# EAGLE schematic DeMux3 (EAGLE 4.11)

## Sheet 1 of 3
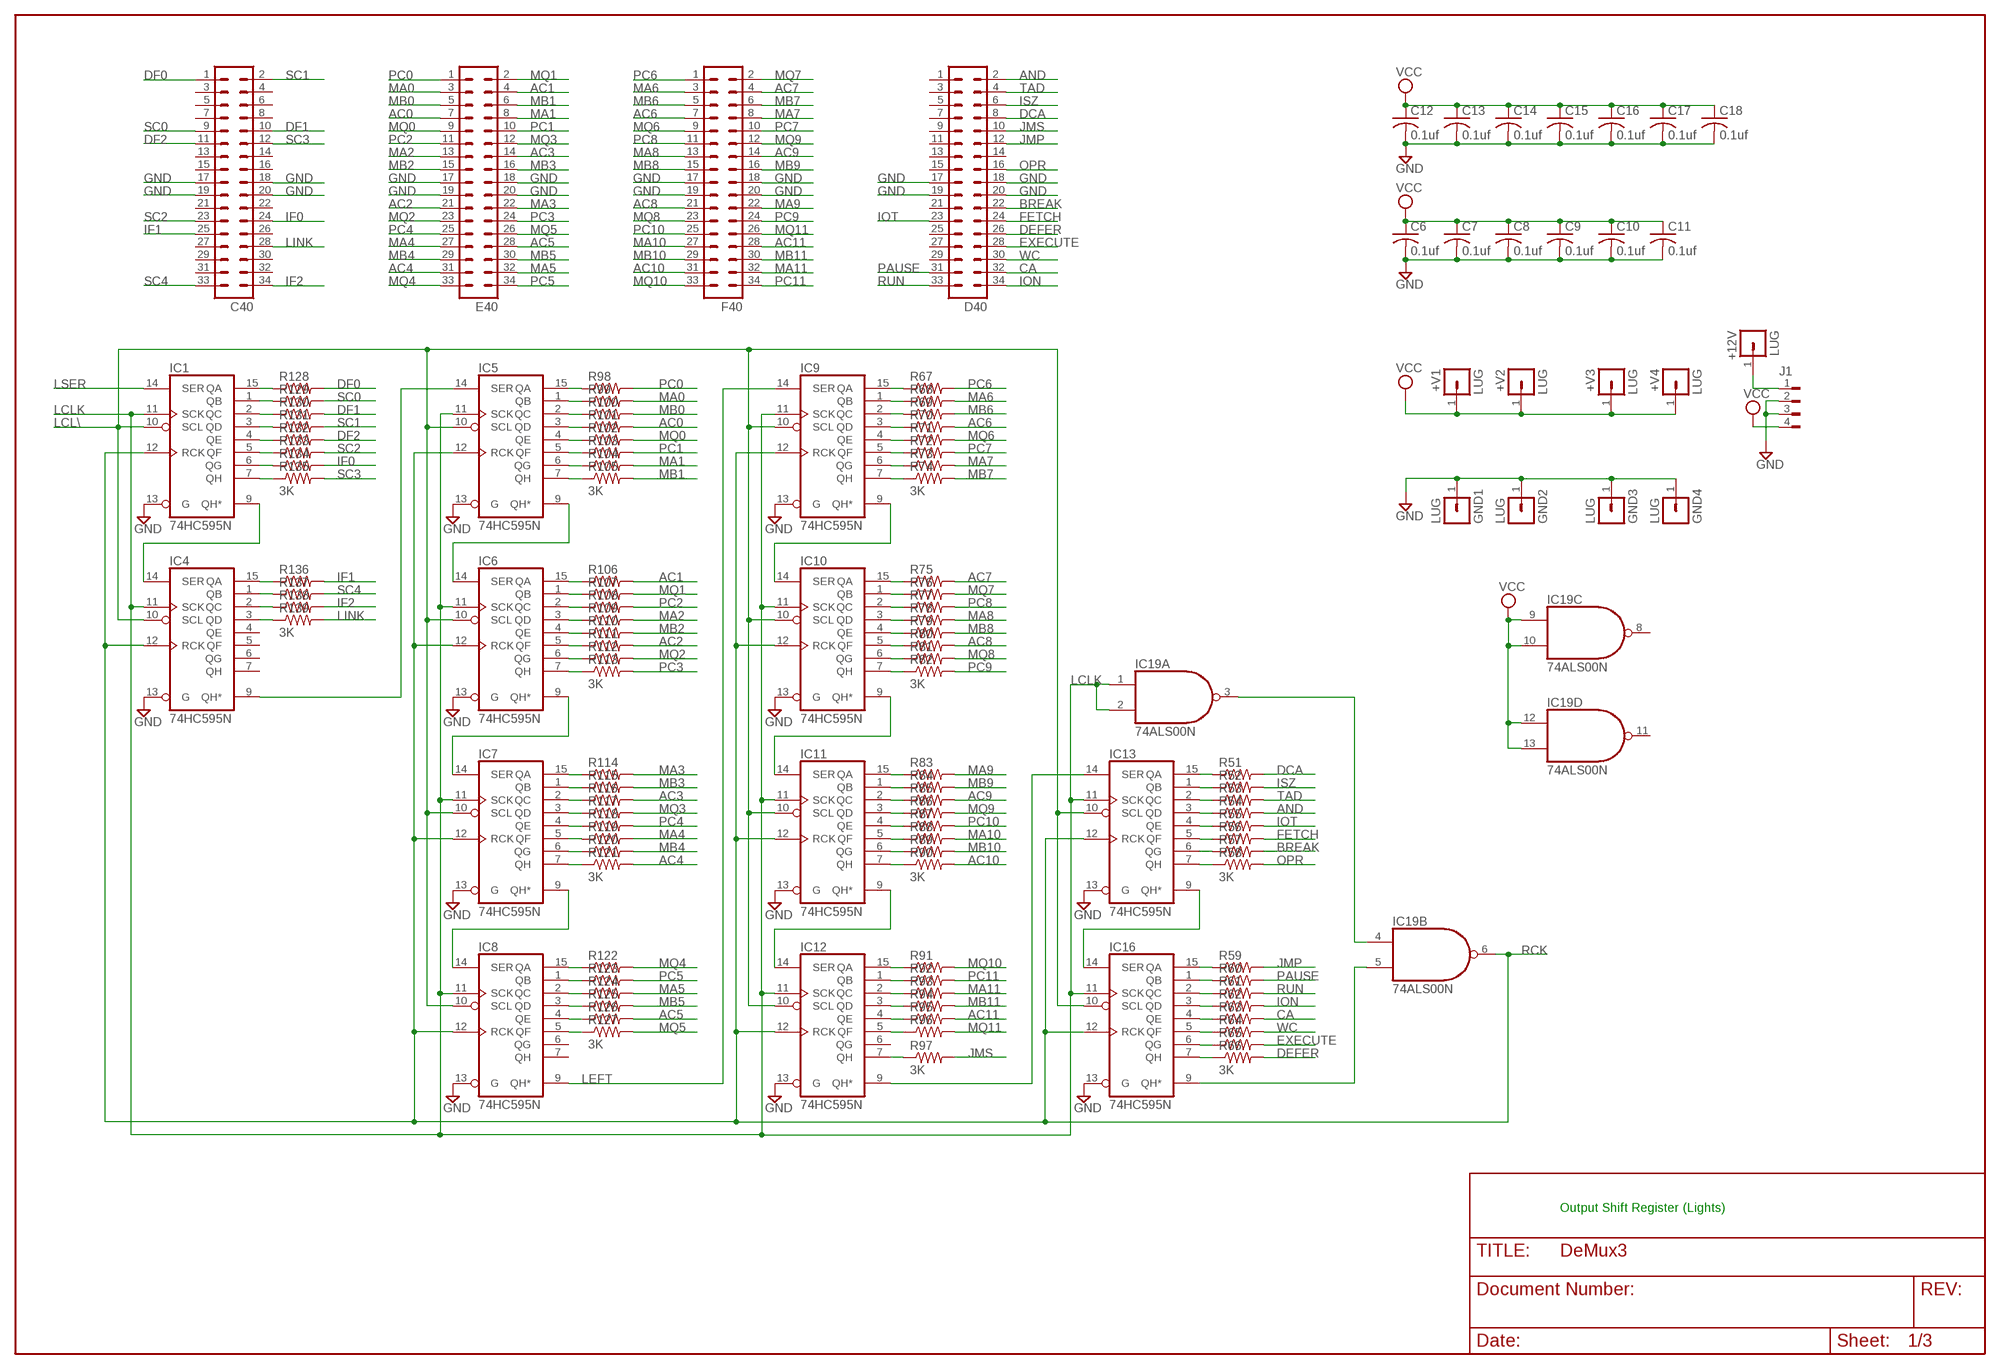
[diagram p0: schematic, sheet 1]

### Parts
+12V  LUG  [SPADELUG]
+V1  LUG  [SPADELUG]
+V2  LUG  [SPADELUG]
+V3  LUG  [SPADELUG]
+V4  LUG  [SPADELUG]
C6  0.1uf  C-US050-025X075  [C050-025X075]
C7  0.1uf  C-US050-025X075  [C050-025X075]
C8  0.1uf  C-US050-025X075  [C050-025X075]
C9  0.1uf  C-US050-025X075  [C050-025X075]
C10  0.1uf  C-US050-025X075  [C050-025X075]
C11  0.1uf  C-US050-025X075  [C050-025X075]
C12  0.1uf  C-US050-025X075  [C050-025X075]
C13  0.1uf  C-US050-025X075  [C050-025X075]
C14  0.1uf  C-US050-025X075  [C050-025X075]
C15  0.1uf  C-US050-025X075  [C050-025X075]
C16  0.1uf  C-US050-025X075  [C050-025X075]
C17  0.1uf  C-US050-025X075  [C050-025X075]
C18  0.1uf  C-US050-025X075  [C050-025X075]
C40  MA17-2  [MA17-2]
D40  MA17-2  [MA17-2]
E40  MA17-2  [MA17-2]
F40  MA17-2  [MA17-2]
GND1  LUG  [SPADELUG]
GND2  LUG  [SPADELUG]
GND3  LUG  [SPADELUG]
GND4  LUG  [SPADELUG]
IC1  74HC595N  74LS595N  [DIL16]
IC4  74HC595N  74LS595N  [DIL16]
IC5  74HC595N  74LS595N  [DIL16]
IC6  74HC595N  74LS595N  [DIL16]
IC7  74HC595N  74LS595N  [DIL16]
IC8  74HC595N  74LS595N  [DIL16]
IC9  74HC595N  74LS595N  [DIL16]
IC10  74HC595N  74LS595N  [DIL16]
IC11  74HC595N  74LS595N  [DIL16]
IC12  74HC595N  74LS595N  [DIL16]
IC13  74HC595N  74LS595N  [DIL16]
IC16  74HC595N  74LS595N  [DIL16]
IC19  74ALS00N  [DIL14]
J1  FLOPPY-4  [FLOPPY-4]
R51  R-US_0207/10  [0207/10]
R52  R-US_0207/10  [0207/10]
R53  R-US_0207/10  [0207/10]
R54  R-US_0207/10  [0207/10]
R55  R-US_0207/10  [0207/10]
R56  R-US_0207/10  [0207/10]
R57  R-US_0207/10  [0207/10]
R58  3K  R-US_0207/10  [0207/10]
R59  R-US_0207/10  [0207/10]
R60  R-US_0207/10  [0207/10]
R61  R-US_0207/10  [0207/10]
R62  R-US_0207/10  [0207/10]
R63  R-US_0207/10  [0207/10]
R64  R-US_0207/10  [0207/10]
R65  R-US_0207/10  [0207/10]
R66  3K  R-US_0207/10  [0207/10]
R67  R-US_0207/10  [0207/10]
R68  R-US_0207/10  [0207/10]
R69  R-US_0207/10  [0207/10]
R70  R-US_0207/10  [0207/10]
R71  R-US_0207/10  [0207/10]
R72  R-US_0207/10  [0207/10]
R73  R-US_0207/10  [0207/10]
R74  3K  R-US_0207/10  [0207/10]
R75  R-US_0207/10  [0207/10]
R76  R-US_0207/10  [0207/10]
R77  R-US_0207/10  [0207/10]
R78  R-US_0207/10  [0207/10]
R79  R-US_0207/10  [0207/10]
R80  R-US_0207/10  [0207/10]
R81  R-US_0207/10  [0207/10]
R82  3K  R-US_0207/10  [0207/10]
R83  R-US_0207/10  [0207/10]
R84  R-US_0207/10  [0207/10]
R85  R-US_0207/10  [0207/10]
R86  R-US_0207/10  [0207/10]
R87  R-US_0207/10  [0207/10]
R88  R-US_0207/10  [0207/10]
R89  R-US_0207/10  [0207/10]
R90  3K  R-US_0207/10  [0207/10]
R91  R-US_0207/10  [0207/10]
R92  R-US_0207/10  [0207/10]
R93  R-US_0207/10  [0207/10]
R94  R-US_0207/10  [0207/10]
R95  R-US_0207/10  [0207/10]
R96  R-US_0207/10  [0207/10]
R97  3K  R-US_0207/10  [0207/10]
R98  R-US_0207/10  [0207/10]
R99  R-US_0207/10  [0207/10]
R100  R-US_0207/10  [0207/10]
R101  R-US_0207/10  [0207/10]
R102  R-US_0207/10  [0207/10]
R103  R-US_0207/10  [0207/10]
R104  R-US_0207/10  [0207/10]
R105  3K  R-US_0207/10  [0207/10]
R106  R-US_0207/10  [0207/10]
R107  R-US_0207/10  [0207/10]
R108  R-US_0207/10  [0207/10]
R109  R-US_0207/10  [0207/10]
R110  R-US_0207/10  [0207/10]
R111  R-US_0207/10  [0207/10]
R112  R-US_0207/10  [0207/10]
R113  3K  R-US_0207/10  [0207/10]
R114  R-US_0207/10  [0207/10]
R115  R-US_0207/10  [0207/10]
R116  R-US_0207/10  [0207/10]
R117  R-US_0207/10  [0207/10]
R118  R-US_0207/10  [0207/10]
R119  R-US_0207/10  [0207/10]
R120  R-US_0207/10  [0207/10]
R121  3K  R-US_0207/10  [0207/10]
R122  R-US_0207/10  [0207/10]
R123  R-US_0207/10  [0207/10]
R124  R-US_0207/10  [0207/10]
R125  R-US_0207/10  [0207/10]
R126  R-US_0207/10  [0207/10]
R127  3K  R-US_0207/10  [0207/10]
R128  R-US_0207/10  [0207/10]
R129  R-US_0207/10  [0207/10]
R130  R-US_0207/10  [0207/10]
R131  R-US_0207/10  [0207/10]
R132  R-US_0207/10  [0207/10]
R133  R-US_0207/10  [0207/10]
R134  R-US_0207/10  [0207/10]
R135  3K  R-US_0207/10  [0207/10]
R136  R-US_0207/10  [0207/10]
R137  R-US_0207/10  [0207/10]
R138  R-US_0207/10  [0207/10]
R139  3K  R-US_0207/10  [0207/10]

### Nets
+12V [supply]: +12V.1 J1.1
AC0: E40.7 R101.2
AC1: E40.4 R106.2
AC2: E40.21 R111.2
AC3: E40.14 R116.2
AC4: E40.31 R121.2
AC5: E40.28 R126.2
AC6: F40.7 R70.2
AC7: F40.4 R75.2
AC8: F40.21 R80.2
AC9: F40.14 R85.2
AC10: F40.31 R90.2
AC11: F40.28 R95.2
AND: D40.2 R54.2
BREAK: D40.22 R57.2
CA: D40.32 R63.2
DCA: D40.8 R51.2
DEFER: D40.26 R66.2
DF0: C40.1 R128.2
DF1: C40.10 R130.2
DF2: C40.11 R132.2
EXECUTE: D40.28 R65.2
FETCH: D40.24 R56.2
GND [supply]: C6.2 C7.2 C8.2 C9.2 C10.2 C11.2 C12.2 C13.2 C14.2 C15.2 C16.2 C17.2 C18.2 C40.17 C40.18 C40.19 C40.20 D40.17 D40.18 D40.19 D40.20 E40.17 E40.18 E40.19 E40.20 F40.17 F40.18 F40.19 F40.20 GND1.1 GND2.1 GND3.1 GND4.1 IC1.13(G) IC4.13(G) IC5.13(G) IC6.13(G) IC7.13(G) IC8.13(G) IC9.13(G) IC10.13(G) IC11.13(G) IC12.13(G) IC13.13(G) IC16.13(G) J1.2 J1.3 ; also sheet 2,3
IF0: C40.24 R134.2
IF1: C40.25 R136.2
IF2: C40.34 R138.2
ION: D40.34 R62.2
IOT: D40.23 R55.2
ISZ: D40.6 R52.2
JMP: D40.12 R59.2
JMS: D40.10 R97.2
LCL\: IC1.10(SCL) IC4.10(SCL) IC5.10(SCL) IC6.10(SCL) IC7.10(SCL) IC8.10(SCL) IC9.10(SCL) IC10.10(SCL) IC11.10(SCL) IC12.10(SCL) IC13.10(SCL) IC16.10(SCL) ; also sheet 3
LCLK: IC1.11(SCK) IC4.11(SCK) IC5.11(SCK) IC6.11(SCK) IC7.11(SCK) IC8.11(SCK) IC9.11(SCK) IC10.11(SCK) IC11.11(SCK) IC12.11(SCK) IC13.11(SCK) IC16.11(SCK) IC19.1(A:I0) IC19.2(A:I1) ; also sheet 3
LEFT: IC8.9(QH*) IC9.14(SER) ; also sheet 3
LINK: C40.28 R139.2
LSER: IC1.14(SER) ; also sheet 3
MA0: E40.3 R99.2
MA1: E40.8 R104.2
MA2: E40.13 R109.2
MA3: E40.22 R114.2
MA4: E40.27 R119.2
MA5: E40.32 R124.2
MA6: F40.3 R68.2
MA7: F40.8 R73.2
MA8: F40.13 R78.2
MA9: F40.22 R83.2
MA10: F40.27 R88.2
MA11: F40.32 R93.2
MB0: E40.5 R100.2
MB1: E40.6 R105.2
MB2: E40.15 R110.2
MB3: E40.16 R115.2
MB4: E40.29 R120.2
MB5: E40.30 R125.2
MB6: F40.5 R69.2
MB7: F40.6 R74.2
MB8: F40.15 R79.2
MB9: F40.16 R84.2
MB10: F40.29 R89.2
MB11: F40.30 R94.2
MQ0: E40.9 R102.2
MQ1: E40.2 R107.2
MQ2: E40.23 R112.2
MQ3: E40.12 R117.2
MQ4: E40.33 R122.2
MQ5: E40.26 R127.2
MQ6: F40.9 R71.2
MQ7: F40.2 R76.2
MQ8: F40.23 R81.2
MQ9: F40.12 R86.2
MQ10: F40.33 R91.2
MQ11: F40.26 R96.2
N$4: IC5.9(QH*) IC6.14(SER)
N$10: IC1.9(QH*) IC4.14(SER)
N$13: IC7.9(QH*) IC8.14(SER)
N$14: IC6.9(QH*) IC7.14(SER)
N$15: IC11.9(QH*) IC12.14(SER)
N$16: IC10.9(QH*) IC11.14(SER)
N$17: IC13.9(QH*) IC16.14(SER)
N$19: IC9.9(QH*) IC10.14(SER)
N$21: IC4.9(QH*) IC5.14(SER)
N$22: IC16.9(QH*) IC19.5(B:I1)
N$23: IC12.9(QH*) IC13.14(SER)
N$24: IC13.15(QA) R51.1
N$25: IC13.1(QB) R52.1
N$26: IC13.2(QC) R53.1
N$27: IC19.3(A:O) IC19.4(B:I0)
N$32: IC13.3(QD) R54.1
N$33: IC13.4(QE) R55.1
N$34: IC13.5(QF) R56.1
N$35: IC13.6(QG) R57.1
N$36: IC13.7(QH) R58.1
N$37: IC16.15(QA) R59.1
N$38: IC16.1(QB) R60.1
N$39: IC16.2(QC) R61.1
N$40: IC16.3(QD) R62.1
N$41: IC16.4(QE) R63.1
N$42: IC16.5(QF) R64.1
N$43: IC16.6(QG) R65.1
N$44: IC16.7(QH) R66.1
N$45: IC9.15(QA) R67.1
N$46: IC9.1(QB) R68.1
N$47: IC9.2(QC) R69.1
N$48: IC9.3(QD) R70.1
N$49: IC9.4(QE) R71.1
N$50: IC9.5(QF) R72.1
N$51: IC9.6(QG) R73.1
N$57: IC9.7(QH) R74.1
N$58: IC12.7(QH) R97.1
N$59: IC12.5(QF) R96.1
N$60: IC12.4(QE) R95.1
N$61: IC12.3(QD) R94.1
N$62: IC12.2(QC) R93.1
N$63: IC12.1(QB) R92.1
N$64: IC12.15(QA) R91.1
N$65: IC10.15(QA) R75.1
N$66: IC10.1(QB) R76.1
N$67: IC10.2(QC) R77.1
N$68: IC10.3(QD) R78.1
N$69: IC10.4(QE) R79.1
N$70: IC10.5(QF) R80.1
N$71: IC10.6(QG) R81.1
N$72: IC10.7(QH) R82.1
N$73: IC11.15(QA) R83.1
N$74: IC11.1(QB) R84.1
N$75: IC11.3(QD) R86.1
N$76: IC11.2(QC) R85.1
N$77: IC11.4(QE) R87.1
N$78: IC11.5(QF) R88.1
N$79: IC11.6(QG) R89.1
N$80: IC11.7(QH) R90.1
N$81: IC8.5(QF) R127.1
N$82: IC8.4(QE) R126.1
N$83: IC8.3(QD) R125.1
N$84: IC8.2(QC) R124.1
N$85: IC8.1(QB) R123.1
N$86: IC8.15(QA) R122.1
N$87: IC7.7(QH) R121.1
N$88: IC7.6(QG) R120.1
N$89: IC7.5(QF) R119.1
N$90: IC7.4(QE) R118.1
N$91: IC7.3(QD) R117.1
N$92: IC7.2(QC) R116.1
N$93: IC7.1(QB) R115.1
N$94: IC7.15(QA) R114.1
N$95: IC5.15(QA) R98.1
N$96: IC5.1(QB) R99.1
N$97: IC5.2(QC) R100.1
N$98: IC5.3(QD) R101.1
N$99: IC5.4(QE) R102.1
N$100: IC5.5(QF) R103.1
N$101: IC5.6(QG) R104.1
N$102: IC5.7(QH) R105.1
N$103: IC6.15(QA) R106.1
N$104: IC6.1(QB) R107.1
N$105: IC6.2(QC) R108.1
N$106: IC6.3(QD) R109.1
N$107: IC6.4(QE) R110.1
N$108: IC6.5(QF) R111.1
N$109: IC6.6(QG) R112.1
N$110: IC6.7(QH) R113.1
N$111: IC1.15(QA) R128.1
N$112: IC1.1(QB) R129.1
N$113: IC1.2(QC) R130.1
N$114: IC1.3(QD) R131.1
N$115: IC1.4(QE) R132.1
N$116: IC1.5(QF) R133.1
N$117: IC1.6(QG) R134.1
N$118: IC1.7(QH) R135.1
N$119: IC4.15(QA) R136.1
N$120: IC4.3(QD) R139.1
N$121: IC4.2(QC) R138.1
N$122: IC4.1(QB) R137.1
OPR: D40.16 R58.2
PAUSE: D40.31 R60.2
PC0: E40.1 R98.2
PC1: E40.10 R103.2
PC2: E40.11 R108.2
PC3: E40.24 R113.2
PC4: E40.25 R118.2
PC5: E40.34 R123.2
PC6: F40.1 R67.2
PC7: F40.10 R72.2
PC8: F40.11 R77.2
PC9: F40.24 R82.2
PC10: F40.25 R87.2
PC11: F40.34 R92.2
RCK: IC1.12(RCK) IC4.12(RCK) IC5.12(RCK) IC6.12(RCK) IC7.12(RCK) IC8.12(RCK) IC9.12(RCK) IC10.12(RCK) IC11.12(RCK) IC12.12(RCK) IC13.12(RCK) IC16.12(RCK) IC19.6(B:O) ; also sheet 3
RUN: D40.33 R61.2
SC0: C40.9 R129.2
SC1: C40.2 R131.2
SC2: C40.23 R133.2
SC3: C40.12 R135.2
SC4: C40.33 R137.2
TAD: D40.4 R53.2
VCC [supply]: +V1.1 +V2.1 +V3.1 +V4.1 C6.1 C7.1 C8.1 C9.1 C10.1 C11.1 C12.1 C13.1 C14.1 C15.1 C16.1 C17.1 C18.1 IC19.9(C:I0) IC19.10(C:I1) IC19.12(D:I0) IC19.13(D:I1) J1.4 ; also sheet 2,3
WC: D40.30 R64.2
Unconnected: C40.3 C40.4 C40.5 C40.6 C40.7 C40.8 C40.13 C40.14 C40.15 C40.16 C40.21 C40.22 C40.26 C40.27 C40.29 C40.30 C40.31 C40.32 D40.1 D40.3 D40.5 D40.7 D40.9 D40.11 D40.13 D40.14 D40.15 D40.21 D40.25 D40.27 D40.29 IC4.4(QE) IC4.5(QF) IC4.6(QG) IC4.7(QH) IC8.6(QG) IC8.7(QH) IC12.6(QG) IC19.8(C:O) IC19.11(D:O)

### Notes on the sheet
- Output Shift Register (Lights)

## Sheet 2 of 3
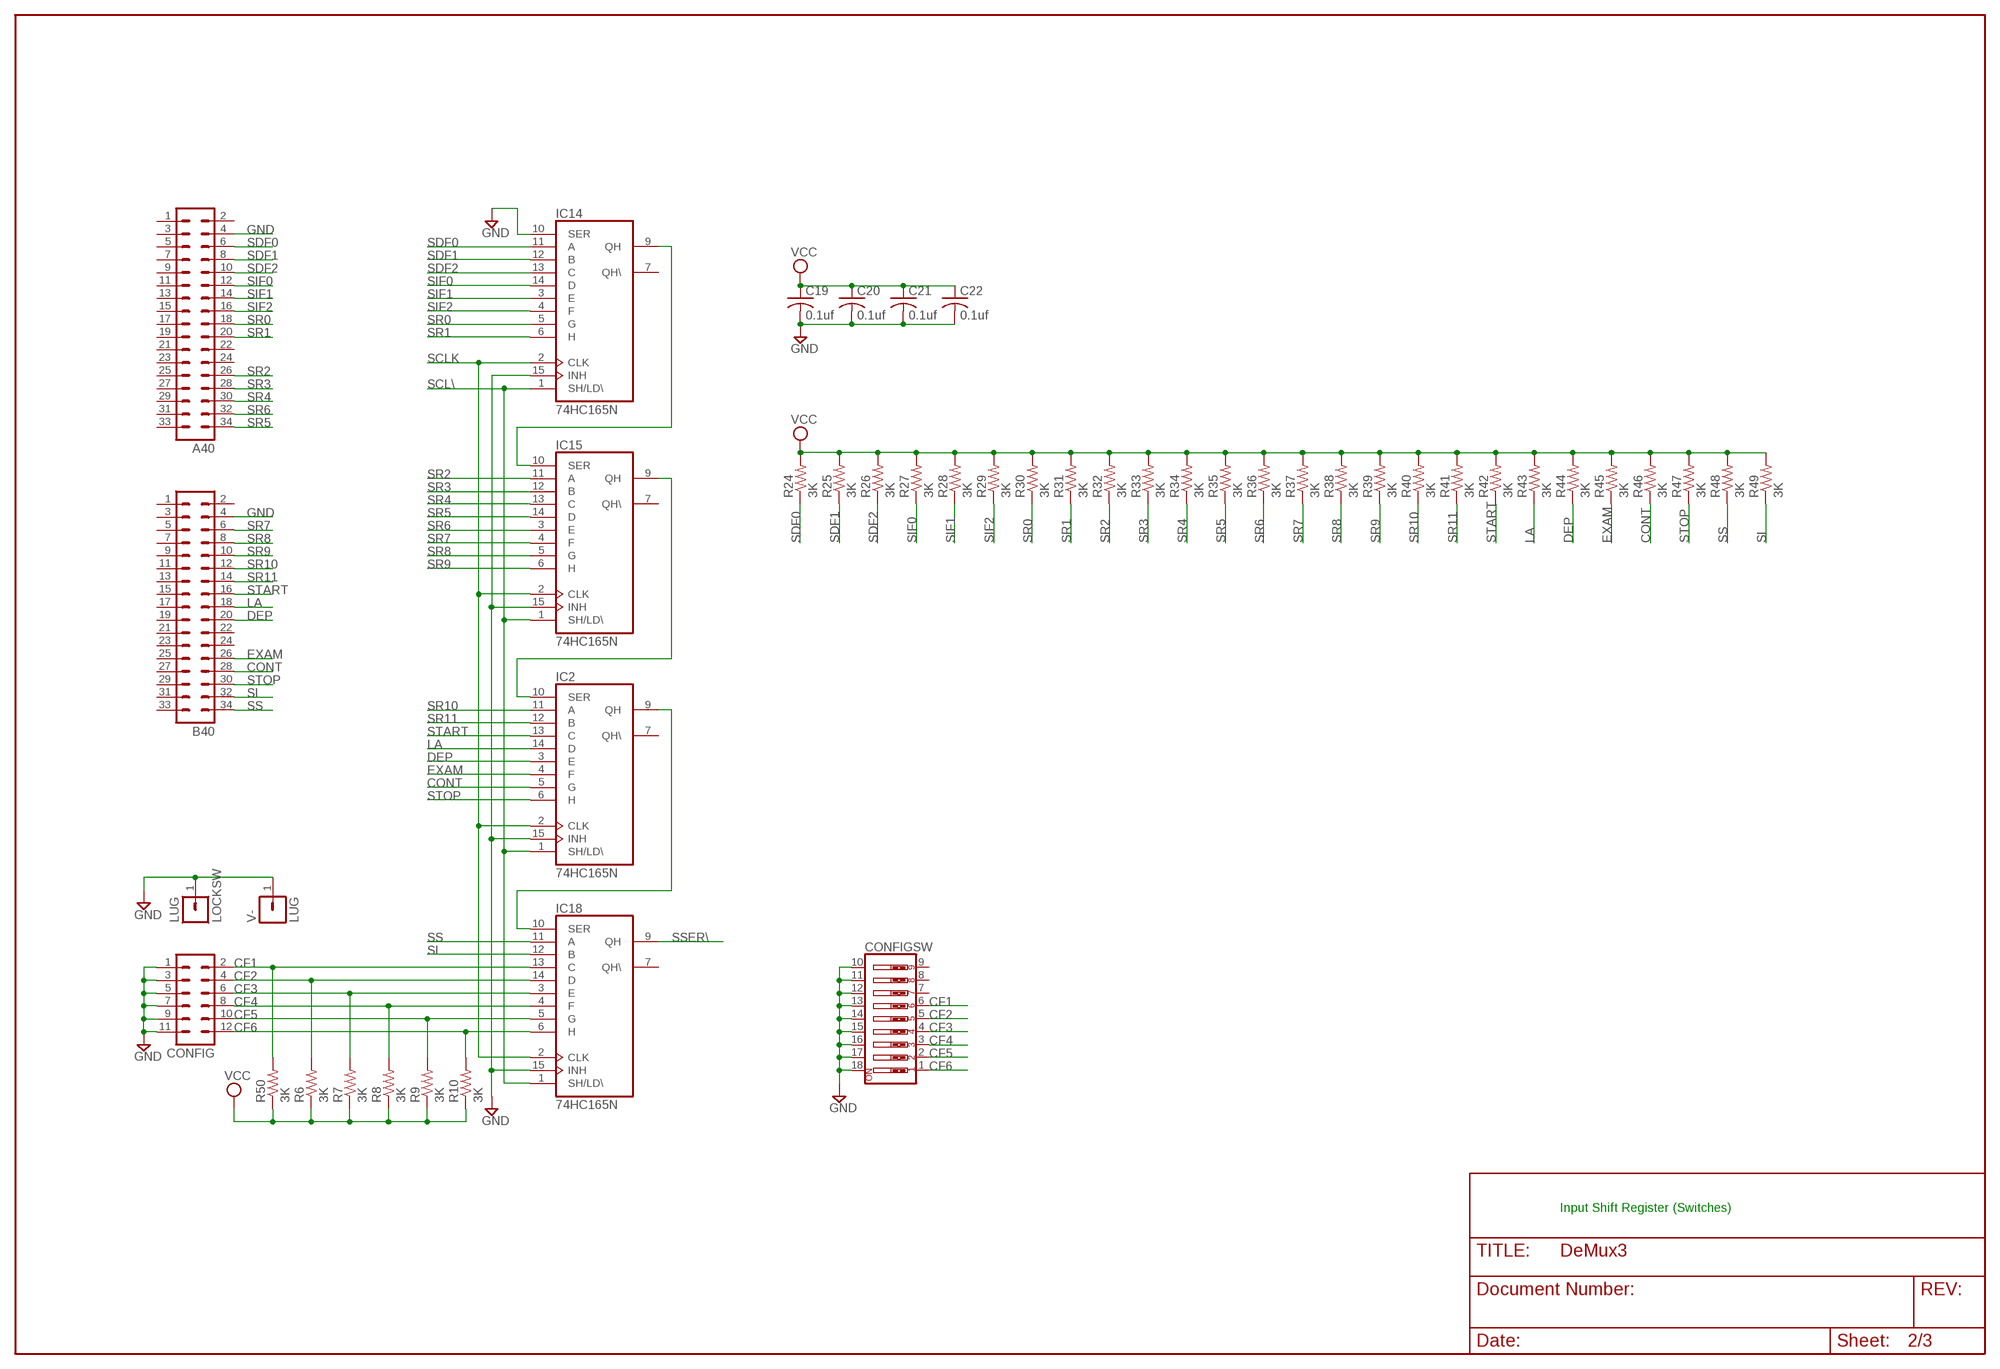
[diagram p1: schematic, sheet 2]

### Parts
A40  MA17-2  [MA17-2]
B40  MA17-2  [MA17-2]
C19  0.1uf  C-US050-025X075  [C050-025X075]
C20  0.1uf  C-US050-025X075  [C050-025X075]
C21  0.1uf  C-US050-025X075  [C050-025X075]
C22  0.1uf  C-US050-025X075  [C050-025X075]
CONFIG  MA06-2  [MA06-2]
CONFIGSW  SW_DIP-9  [EDG-09]
IC2  74HC165N  74LS165N  [DIL16]
IC14  74HC165N  74LS165N  [DIL16]
IC15  74HC165N  74LS165N  [DIL16]
IC18  74HC165N  74LS165N  [DIL16]
LOCKSW  LUG  [SPADELUG]
R6  3K  R-US_0207/10  [0207/10]
R7  3K  R-US_0207/10  [0207/10]
R8  3K  R-US_0207/10  [0207/10]
R9  3K  R-US_0207/10  [0207/10]
R10  3K  R-US_0207/10  [0207/10]
R24  3K  R-US_0207/10  [0207/10]
R25  3K  R-US_0207/10  [0207/10]
R26  3K  R-US_0207/10  [0207/10]
R27  3K  R-US_0207/10  [0207/10]
R28  3K  R-US_0207/10  [0207/10]
R29  3K  R-US_0207/10  [0207/10]
R30  3K  R-US_0207/10  [0207/10]
R31  3K  R-US_0207/10  [0207/10]
R32  3K  R-US_0207/10  [0207/10]
R33  3K  R-US_0207/10  [0207/10]
R34  3K  R-US_0207/10  [0207/10]
R35  3K  R-US_0207/10  [0207/10]
R36  3K  R-US_0207/10  [0207/10]
R37  3K  R-US_0207/10  [0207/10]
R38  3K  R-US_0207/10  [0207/10]
R39  3K  R-US_0207/10  [0207/10]
R40  3K  R-US_0207/10  [0207/10]
R41  3K  R-US_0207/10  [0207/10]
R42  3K  R-US_0207/10  [0207/10]
R43  3K  R-US_0207/10  [0207/10]
R44  3K  R-US_0207/10  [0207/10]
R45  3K  R-US_0207/10  [0207/10]
R46  3K  R-US_0207/10  [0207/10]
R47  3K  R-US_0207/10  [0207/10]
R48  3K  R-US_0207/10  [0207/10]
R49  3K  R-US_0207/10  [0207/10]
R50  3K  R-US_0207/10  [0207/10]
V-  LUG  [SPADELUG]

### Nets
CF1: CONFIG.2 CONFIGSW.6 IC18.13(C) R50.2
CF2: CONFIG.4 CONFIGSW.5 IC18.14(D) R6.2
CF3: CONFIG.6 CONFIGSW.4 IC18.3(E) R7.2
CF4: CONFIG.8 CONFIGSW.3 IC18.4(F) R8.2
CF5: CONFIG.10 CONFIGSW.2 IC18.5(G) R9.2
CF6: CONFIG.12 CONFIGSW.1 IC18.6(H) R10.2
CONT: B40.28 IC2.5(G) R46.1
DEP: B40.20 IC2.3(E) R44.1
EXAM: B40.26 IC2.4(F) R45.1
GND [supply]: A40.4 B40.4 C19.2 C20.2 C21.2 C22.2 CONFIG.1 CONFIG.3 CONFIG.5 CONFIG.7 CONFIG.9 CONFIG.11 CONFIGSW.10 CONFIGSW.11 CONFIGSW.12 CONFIGSW.13 CONFIGSW.14 CONFIGSW.15 CONFIGSW.16 CONFIGSW.17 CONFIGSW.18 IC2.15(INH) IC14.10(SER) IC14.15(INH) IC15.15(INH) IC18.15(INH) LOCKSW.1 V-.1 ; also sheet 1,3
LA: B40.18 IC2.14(D) R43.1
N$1: IC14.9(QH) IC15.10(SER)
N$2: IC2.10(SER) IC15.9(QH)
N$3: IC2.9(QH) IC18.10(SER)
SCL\: IC2.1(SH/LD\) IC14.1(SH/LD\) IC15.1(SH/LD\) IC18.1(SH/LD\) ; also sheet 3
SCLK: IC2.2(CLK) IC14.2(CLK) IC15.2(CLK) IC18.2(CLK) ; also sheet 3
SDF0: A40.6 IC14.11(A) R24.1
SDF1: A40.8 IC14.12(B) R25.1
SDF2: A40.10 IC14.13(C) R26.1
SI: B40.32 IC18.12(B) R49.1
SIF0: A40.12 IC14.14(D) R27.1
SIF1: A40.14 IC14.3(E) R28.1
SIF2: A40.16 IC14.4(F) R29.1
SR0: A40.18 IC14.5(G) R30.1
SR1: A40.20 IC14.6(H) R31.1
SR2: A40.26 IC15.11(A) R32.1
SR3: A40.28 IC15.12(B) R33.1
SR4: A40.30 IC15.13(C) R34.1
SR5: A40.34 IC15.14(D) R35.1
SR6: A40.32 IC15.3(E) R36.1
SR7: B40.6 IC15.4(F) R37.1
SR8: B40.8 IC15.5(G) R38.1
SR9: B40.10 IC15.6(H) R39.1
SR10: B40.12 IC2.11(A) R40.1
SR11: B40.14 IC2.12(B) R41.1
SS: B40.34 IC18.11(A) R48.1
SSER\: IC18.9(QH) ; also sheet 3
START: B40.16 IC2.13(C) R42.1
STOP: B40.30 IC2.6(H) R47.1
VCC [supply]: C19.1 C20.1 C21.1 C22.1 R6.1 R7.1 R8.1 R9.1 R10.1 R24.2 R25.2 R26.2 R27.2 R28.2 R29.2 R30.2 R31.2 R32.2 R33.2 R34.2 R35.2 R36.2 R37.2 R38.2 R39.2 R40.2 R41.2 R42.2 R43.2 R44.2 R45.2 R46.2 R47.2 R48.2 R49.2 R50.1 ; also sheet 1,3
Unconnected: A40.1 A40.2 A40.3 A40.5 A40.7 A40.9 A40.11 A40.13 A40.15 A40.17 A40.19 A40.21 A40.22 A40.23 A40.24 A40.25 A40.27 A40.29 A40.31 A40.33 B40.1 B40.2 B40.3 B40.5 B40.7 B40.9 B40.11 B40.13 B40.15 B40.17 B40.19 B40.21 B40.22 B40.23 B40.24 B40.25 B40.27 B40.29 B40.31 B40.33 CONFIGSW.7 CONFIGSW.8 CONFIGSW.9 IC2.7(QH\) IC14.7(QH\) IC15.7(QH\) IC18.7(QH\)

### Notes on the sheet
- Input Shift Register (Switches)

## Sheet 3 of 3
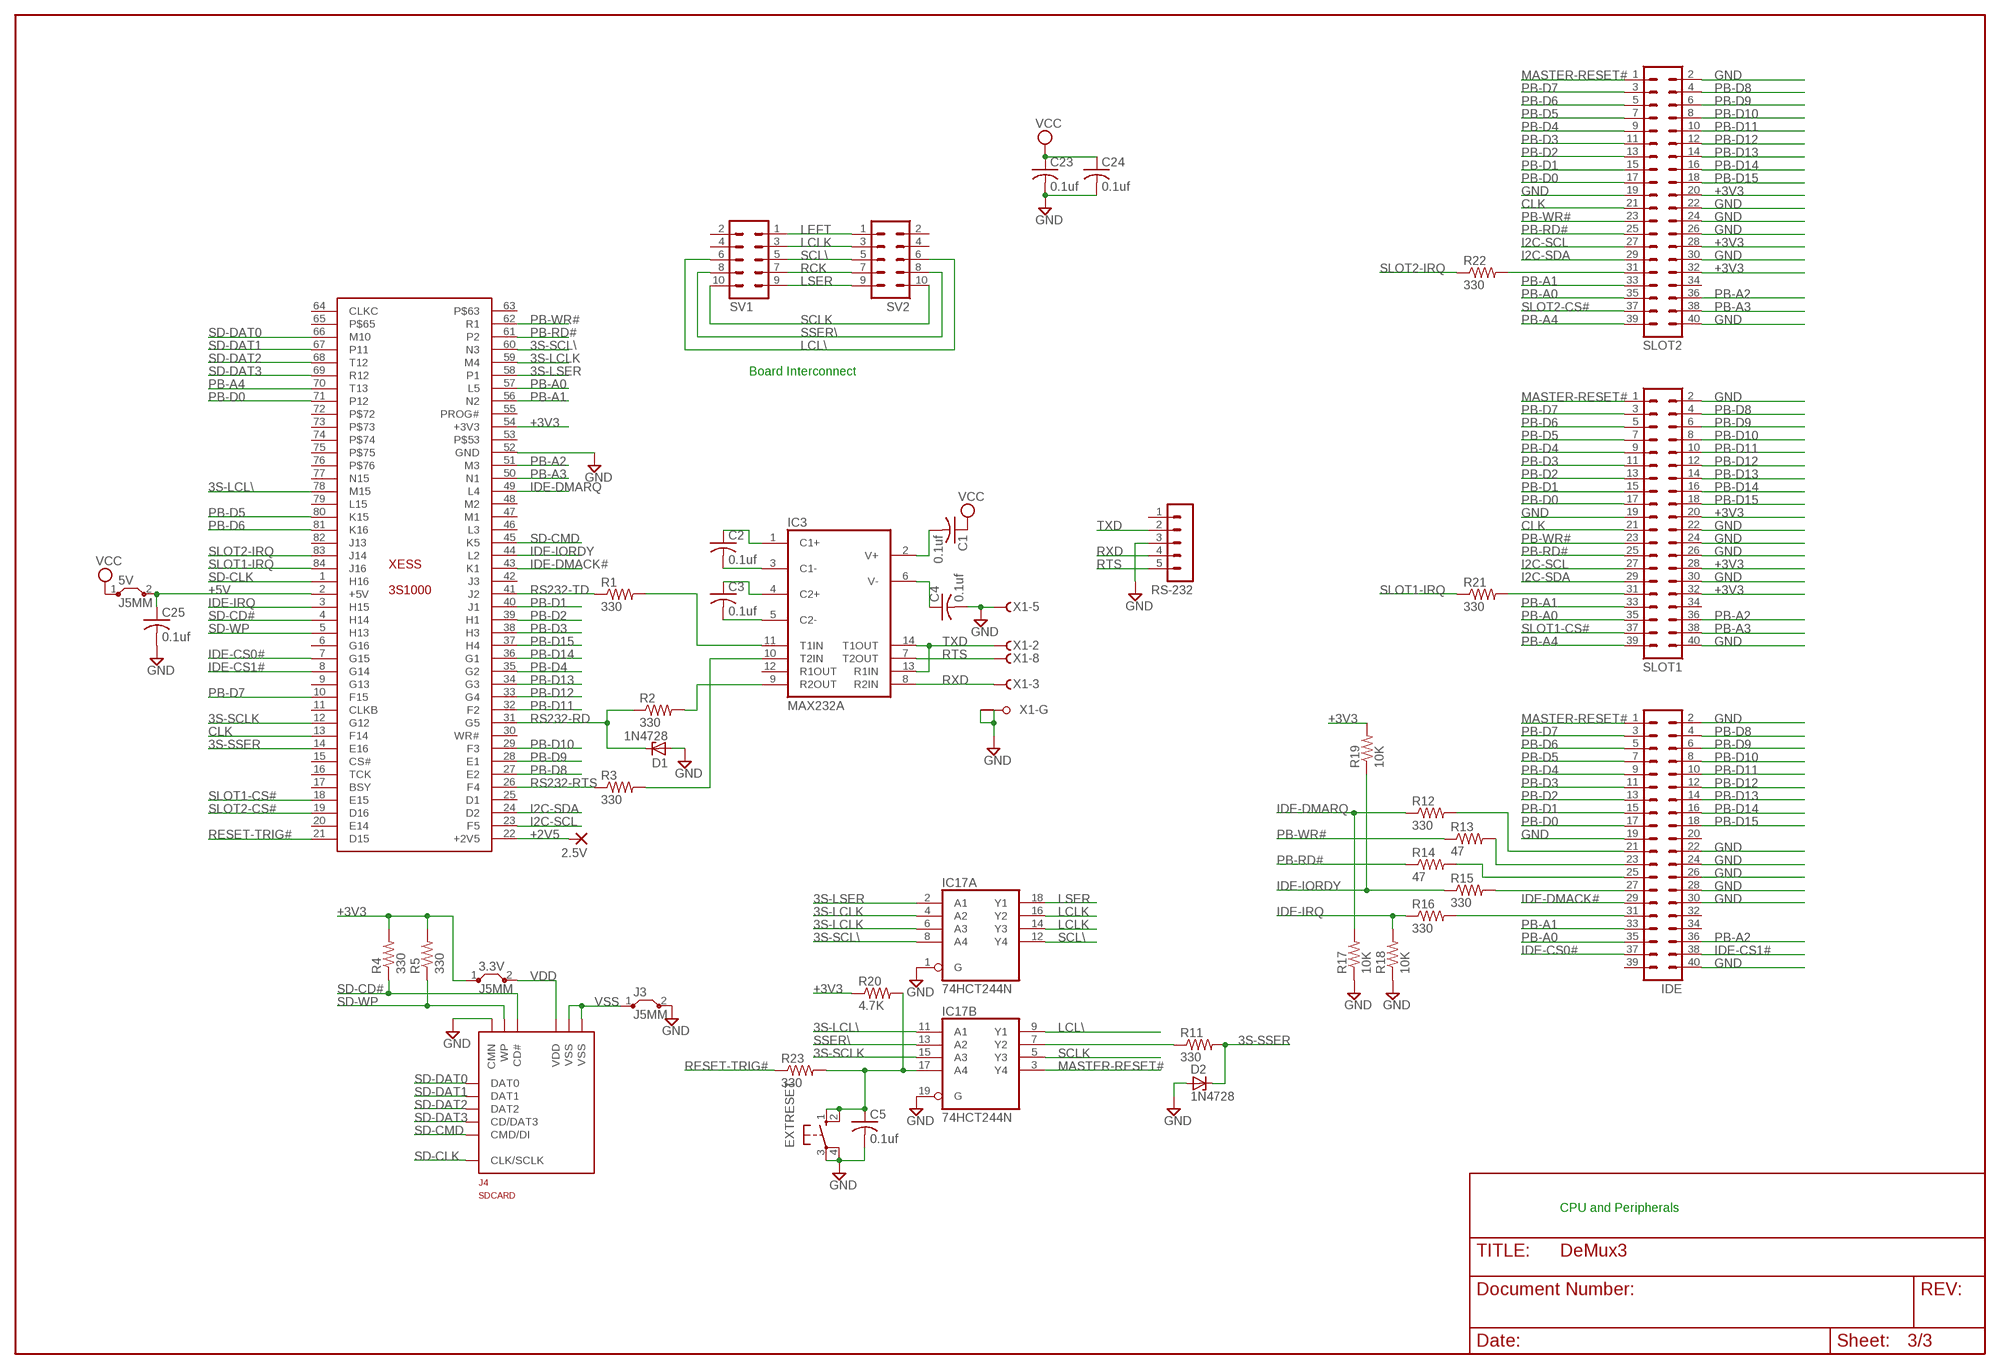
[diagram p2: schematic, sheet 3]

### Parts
2.5V  1,6/0,8  [1,6/0,8]
3.3V  J5MM  [05]
5V  J5MM  [05]
C1  0.1uf  C-US050-025X075  [C050-025X075]
C2  0.1uf  C-US050-025X075  [C050-025X075]
C3  0.1uf  C-US050-025X075  [C050-025X075]
C4  0.1uf  C-US050-025X075  [C050-025X075]
C5  0.1uf  C-US050-025X075  [C050-025X075]
C23  0.1uf  C-US050-025X075  [C050-025X075]
C24  0.1uf  C-US050-025X075  [C050-025X075]
C25  0.1uf  C-US050-025X075  [C050-025X075]
D1  1N4728  [DO41Z10]
D2  1N4728  [DO41Z10]
EXTRESET  40-XX  [B3F-40XX]
IC3  MAX232A  MAX232  [DIL16]
IC17  74HCT244N  [DIL20]
IDE  MA20-2  [MA20-2]
J3  J5MM  [05]
J4  SDCARD  [SCDA5A]
R1  330  R-US_0207/10  [0207/10]
R2  330  R-US_0207/10  [0207/10]
R3  330  R-US_0207/10  [0207/10]
R4  330  R-US_0207/10  [0207/10]
R5  330  R-US_0207/10  [0207/10]
R11  330  R-US_0207/10  [0207/10]
R12  330  R-US_0207/10  [0207/10]
R13  47  R-US_0207/10  [0207/10]
R14  47  R-US_0207/10  [0207/10]
R15  330  R-US_0207/10  [0207/10]
R16  330  R-US_0207/10  [0207/10]
R17  10K  R-US_0207/10  [0207/10]
R18  10K  R-US_0207/10  [0207/10]
R19  10K  R-US_0207/10  [0207/10]
R20  4.7K  R-US_0207/10  [0207/10]
R21  330  R-US_0207/10  [0207/10]
R22  330  R-US_0207/10  [0207/10]
R23  330  R-US_0207/10  [0207/10]
RS-232  MA05-1  [MA05-1]
SLOT1  MA20-2  [MA20-2]
SLOT2  MA20-2  [MA20-2]
SV1  MA05-2  [MA05-2]
SV2  MA05-2  [MA05-2]
X1  F09HPS  [F09HP]
XESS  3S1000  [3S1000]

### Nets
3S-LCL\: IC17.11(B:A1) XESS.78(M15)
3S-LCLK: IC17.4(A:A2) IC17.6(A:A3) XESS.59(M4)
3S-LSER: IC17.2(A:A1) XESS.58(P1)
3S-SCL\: IC17.8(A:A4) XESS.60(N3)
3S-SCLK: IC17.15(B:A3) XESS.12(G12)
3S-SSER: D2.C R11.2 XESS.14(E16)
+2V5 [supply]: 2.5V.1(P) XESS.22(+2V5)
+3V3 [supply]: 3.3V.1 R4.2 R5.2 R19.2 R20.1 SLOT1.20 SLOT1.28 SLOT1.32 SLOT2.20 SLOT2.28 SLOT2.32 XESS.54(+3V3)
+5V [supply]: 5V.2 C25.1 XESS.2(+5V)
CLK: SLOT1.21 SLOT2.21 XESS.13(F14)
GND [supply]: C4.2 C5.2 C23.2 C24.2 C25.2 D1.A D2.A EXTRESET.3(P) EXTRESET.4(P1) IC17.1(A:G) IC17.19(B:G) IDE.2 IDE.19 IDE.22 IDE.24 IDE.26 IDE.28 IDE.30 IDE.40 J3.2 J4.11(CMN) R17.1 R18.1 RS-232.3 SLOT1.2 SLOT1.19 SLOT1.22 SLOT1.24 SLOT1.26 SLOT1.30 SLOT1.40 SLOT2.2 SLOT2.19 SLOT2.22 SLOT2.24 SLOT2.26 SLOT2.30 SLOT2.40 X1.5(-5:F) X1.G1(-G:G1) X1.G2(-G:G2) XESS.52(GND) ; also sheet 1,2
I2C-SCL: SLOT1.27 SLOT2.27 XESS.23(F5)
I2C-SDA: SLOT1.29 SLOT2.29 XESS.24(D2)
IDE-CS0#: IDE.37 XESS.7(G15)
IDE-CS1#: IDE.38 XESS.8(G14)
IDE-DMACK#: IDE.29 XESS.43(K1)
IDE-DMARQ: R12.1 R17.2 XESS.49(L4)
IDE-IORDY: R15.1 R19.1 XESS.44(L2)
IDE-IRQ: R16.1 R18.2 XESS.3(H15)
LCL\: IC17.9(B:Y1) SV1.6 SV2.6 ; also sheet 1
LCLK: IC17.14(A:Y3) IC17.16(A:Y2) SV1.3 SV2.3 ; also sheet 1
LEFT: SV1.1 SV2.1 ; also sheet 1
LSER: IC17.18(A:Y1) SV1.9 SV2.9 ; also sheet 1
MASTER-RESET#: IC17.3(B:Y4) IDE.1 SLOT1.1 SLOT2.1
N$5: IC3.10(T2IN) R3.2
N$6: IC3.11(T1IN) R1.2
N$7: IC3.9(R2OUT) R2.2
N$8: C1.2 IC3.2(V+)
N$9: C2.2 IC3.3(C1-)
N$11: C2.1 IC3.1(C1+)
N$12: C4.1 IC3.6(V-)
N$18: C3.1 IC3.4(C2+)
N$20: C3.2 IC3.5(C2-)
N$28: IC17.7(B:Y2) R11.1
N$29: R21.2 SLOT1.31
N$30: R22.2 SLOT2.31
N$31: C5.1 EXTRESET.1(S) EXTRESET.2(S1) IC17.17(B:A4) R20.2 R23.2
N$52: IDE.31 R16.2
N$53: IDE.27 R15.2
N$54: IDE.25 R14.2
N$55: IDE.23 R13.2
N$56: IDE.21 R12.2
PB-A0: IDE.35 SLOT1.35 SLOT2.35 XESS.57(L5)
PB-A1: IDE.33 SLOT1.33 SLOT2.33 XESS.56(N2)
PB-A2: IDE.36 SLOT1.36 SLOT2.36 XESS.51(M3)
PB-A3: SLOT1.38 SLOT2.38 XESS.50(N1)
PB-A4: SLOT1.39 SLOT2.39 XESS.70(T13)
PB-D0: IDE.17 SLOT1.17 SLOT2.17 XESS.71(P12)
PB-D1: IDE.15 SLOT1.15 SLOT2.15 XESS.40(J1)
PB-D2: IDE.13 SLOT1.13 SLOT2.13 XESS.39(H1)
PB-D3: IDE.11 SLOT1.11 SLOT2.11 XESS.38(H3)
PB-D4: IDE.9 SLOT1.9 SLOT2.9 XESS.35(G2)
PB-D5: IDE.7 SLOT1.7 SLOT2.7 XESS.80(K15)
PB-D6: IDE.5 SLOT1.5 SLOT2.5 XESS.81(K16)
PB-D7: IDE.3 SLOT1.3 SLOT2.3 XESS.10(F15)
PB-D8: IDE.4 SLOT1.4 SLOT2.4 XESS.27(E2)
PB-D9: IDE.6 SLOT1.6 SLOT2.6 XESS.28(E1)
PB-D10: IDE.8 SLOT1.8 SLOT2.8 XESS.29(F3)
PB-D11: IDE.10 SLOT1.10 SLOT2.10 XESS.32(F2)
PB-D12: IDE.12 SLOT1.12 SLOT2.12 XESS.33(G4)
PB-D13: IDE.14 SLOT1.14 SLOT2.14 XESS.34(G3)
PB-D14: IDE.16 SLOT1.16 SLOT2.16 XESS.36(G1)
PB-D15: IDE.18 SLOT1.18 SLOT2.18 XESS.37(H4)
PB-RD#: R14.1 SLOT1.25 SLOT2.25 XESS.61(P2)
PB-WR#: R13.1 SLOT1.23 SLOT2.23 XESS.62(R1)
RCK: SV1.7 SV2.7 ; also sheet 1
RESET-TRIG#: R23.1 XESS.21(D15)
RS232-RD: D1.C R2.1 XESS.31(G5)
RS232-RTS: R3.1 XESS.26(F4)
RS232-TD: R1.1 XESS.41(J2)
RTS: IC3.7(T2OUT) RS-232.5 X1.8(-8:F)
RXD: IC3.8(R2IN) RS-232.4 X1.3(-3:F)
SCL\: IC17.12(A:Y4) SV1.5 SV2.5 ; also sheet 2
SCLK: IC17.5(B:Y3) SV1.10 SV2.10 ; also sheet 2
SD-CD#: J4.10(CD#) R4.1 XESS.4(H14)
SD-CLK: J4.5(CLK/SCLK) XESS.1(H16)
SD-CMD: J4.2(CMD/DI) XESS.45(K5)
SD-DAT0: J4.7(DAT0) XESS.66(M10)
SD-DAT1: J4.8(DAT1) XESS.67(P11)
SD-DAT2: J4.9(DAT2) XESS.68(T12)
SD-DAT3: J4.1(CD/DAT3) XESS.69(R12)
SD-WP: J4.12(WP) R5.1 XESS.5(H13)
SLOT1-CS#: SLOT1.37 XESS.18(E15)
SLOT1-IRQ: R21.1 XESS.84(J16)
SLOT2-CS#: SLOT2.37 XESS.19(D16)
SLOT2-IRQ: R22.1 XESS.83(J14)
SSER\: IC17.13(B:A2) SV1.8 SV2.8 ; also sheet 2
TXD: IC3.13(R1IN) IC3.14(T1OUT) RS-232.2 X1.2(-2:F)
VCC [supply]: 5V.1 C1.1 C23.1 C24.1 ; also sheet 1,2
VDD [supply]: 3.3V.2 J4.4(VDD)
VSS [supply]: J3.1 J4.3(VSS) J4.6(VSS)
Unconnected: IC3.12(R1OUT) IDE.20 IDE.32 IDE.34 IDE.39 RS-232.1 SLOT1.34 SLOT2.34 SV1.2 SV1.4 SV2.2 SV2.4 X1.1(-1:F) X1.4(-4:F) X1.6(-6:F) X1.7(-7:F) X1.9(-9:F) XESS.6(G16) XESS.9(G13) XESS.11(CLKB) XESS.15(CS#) XESS.16(TCK) XESS.17(BSY) XESS.20(E14) XESS.25(D1) XESS.30(WR#) XESS.42(J3) XESS.46(L3) XESS.47(M1) XESS.48(M2) XESS.53 XESS.55(PROG#) XESS.63 XESS.64(CLKC) XESS.65 XESS.72 XESS.73 XESS.74 XESS.75 XESS.76 XESS.77(N15) XESS.79(L15) XESS.82(J13)

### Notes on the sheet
- Board Interconnect
- CPU and Peripherals

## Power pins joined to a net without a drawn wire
GND: IC1.8(GND) IC2.8(GND) IC3.15(GND) IC4.8(GND) IC5.8(GND) IC6.8(GND) IC7.8(GND) IC8.8(GND) IC9.8(GND) IC10.8(GND) IC11.8(GND) IC12.8(GND) IC13.8(GND) IC14.8(GND) IC15.8(GND) IC16.8(GND) IC17.10(P:GND) IC18.8(GND) IC19.7(P:GND) J4.13(GND) J4.14(GND)
VCC: IC1.16(VCC) IC2.16(VCC) IC3.16(VCC) IC4.16(VCC) IC5.16(VCC) IC6.16(VCC) IC7.16(VCC) IC8.16(VCC) IC9.16(VCC) IC10.16(VCC) IC11.16(VCC) IC12.16(VCC) IC13.16(VCC) IC14.16(VCC) IC15.16(VCC) IC16.16(VCC) IC17.20(P:VCC) IC18.16(VCC) IC19.14(P:VCC)

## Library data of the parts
2.5V = wirepad:1,6/0,8: THROUGH-HOLE PAD
3.3V 5V J3 = jumper:J: Bridge
+12V +V1-+V4 GND1-GND4 LOCKSW V- = dec-con:LUG: Spade Lug
A40 B40 C40 D40 E40 F40 = con-lstb:MA17-2: PIN HEADER
C1-C25 = rcl:C-US: CAPACITOR, American symbol
CONFIG = con-lstb:MA06-2: PIN HEADER
CONFIGSW = special:SW_DIP-9: DIP SWITCH
D1 D2 = diode:1N4728: Z DIODE
EXTRESET = switch-omron:40-XX: OMRON SWITCH
IC1 IC4-IC13 IC16 = 74xx-jameco:74*595: 8-bit SHIFT REGISTER, output latch
IC2 IC14 IC15 IC18 = 74xx-jameco:74*165: 8-bit parallel load SHIFT REGISTER
IC3 = maxim:MAX232: RS232 TRANSEIVER
IC17 = 74xx-jameco:74*244: Octal BUFFER and LINE DRIVER, 3-state
IC19 = 74xx-jameco:74*00: Quad 2-input NAND gate
IDE SLOT1 SLOT2 = con-lstb:MA20-2: PIN HEADER
J1 = con-amp:FLOPPY-4: MATE N-LOCK
J4 = sdcards:SDCARD: SD Card Holder
R1-R139 = rcl:R-US_: RESISTOR, American symbol
RS-232 = con-lstb:MA05-1: PIN HEADER
SV1 SV2 = con-lstb:MA05-2: PIN HEADER
X1 = con-subd:F09HPS: SUB-D
XESS = xess:3S1000

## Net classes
1 supply: width 1.016 mm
